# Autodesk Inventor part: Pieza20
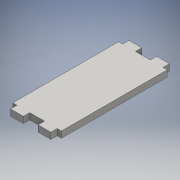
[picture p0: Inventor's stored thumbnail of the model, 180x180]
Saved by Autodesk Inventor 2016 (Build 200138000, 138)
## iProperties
Created: 2016-06
Part Number: Pieza20
Material: Genérico
Document SubType Name: Modeling
Designer: adm
Density: 1 g/cm^3
Appearance: Valor por defecto
Author: adm
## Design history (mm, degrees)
sketch "Boceto1"
  geometry: L1 (11.5, 25)-(11.5, -25); L2 (-11.5, -25)-(-11.5, 25); L3 (-11.5, 25)-(11.5, -25); L4 (11.5, 25)-(-11.5, -25); L5 (3.5, 25)-(3.5, 28); L6 (3.5, 28)-(9.5, 28); L7 (9.5, 28)-(9.5, 25); L8 (-3.5, 25)-(-3.5, 28); L9 (-3.5, 28)-(-9.5, 28); L10 (-9.5, 28)-(-9.5, 25); L11 (-11.5, 25)-(-9.5, 25); L12 (-3.5, 25)-(3.5, 25); L13 (9.5, 25)-(11.5, 25); L14 (9.5, -28)-(9.5, -25); L15 (3.5, -28)-(9.5, -28); L16 (-3.5, -25)-(-3.5, -28); L17 (-3.5, -28)-(-9.5, -28); L18 (-9.5, -28)-(-9.5, -25); L19 (3.5, -25)-(3.5, -28); L20 (-9.5, -25)-(-11.5, -25); L21 (11.5, -25)-(9.5, -25); L22 (3.5, -25)-(-3.5, -25); 1 further point
  constraints: 44 end point, 11 parallel, 3 horizontal, 3 perpendicular, 2 midpoint
  dimensions: "d0" = 50 distance of L1.start L1.end; "d1" = 23 distance of L1.end L2.start; "d2" = 3 distance of L6.end L7.end; "d3" = 2 distance between parallel lines of L7 L1; "d4" = 6 distance of L5.end L6.end
extrude "Extrusión1" new body sketch "Boceto1" distance "d5" = 3; taper "d6" = 0 deg
node "Sólido1"
